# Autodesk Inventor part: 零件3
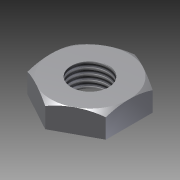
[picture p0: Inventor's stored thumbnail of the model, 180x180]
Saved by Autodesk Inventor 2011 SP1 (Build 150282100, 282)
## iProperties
Created: 2014-02
Part Number: 零件3
Document SubType Name: Modeling
Designer: yn
Density: 1 g/cm^3
Author: yn
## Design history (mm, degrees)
sketch "草图1"
  geometry: L1 (-12.633, 0)-(-12.633, -7.495); L2 (-12.633, -7.495)-(-0.037, -14.374); L3 (-0.037, -14.374)-(12.633, -7.539); L4 (12.633, -7.539)-(12.633, 0); L5 (-12.633, 0)-(-12.633, 7.495); L6 (-12.633, 7.495)-(-0.037, 14.374); L7 (-0.037, 14.374)-(12.633, 7.539); L8 (12.633, 7.539)-(12.633, 0); C1 r 6 at (0, 0); A1 r 12.633 centre (0, 0) between (12.633, 0) and (-12.633, 0); 1 further point
  constraints: 16 end point, 4 tangent, 2 centre point, 2 coincident, 2 point on circle, 1 parallel, 1 vertical
  dimensions: "d0" = 12 diameter of C1
extrude "拉伸1" new body sketch "草图1" distance "d1" = 10; taper "d2" = 0 deg
feature "螺纹1" dims "d3" = 10, "d4" = 0
sketch "草图3"
  geometry: L1 (-14.374, 10)-(-7.495, 10) reference; L2 (7.495, 10)-(14.374, 10) reference; L3 (-7.495, 10)-(7.495, 10) reference; L4 (14.374, 0)-(7.495, 0) reference; L5 (-7.495, 0)-(-14.374, 0) reference; L6 (7.495, 0)-(-7.495, 0) reference; L7 (0, 10.762)-(0, -41.632); A1 r 26.197 centre (0, -15.435) between (0, 10.762) and (0, -41.632); 1 further point
  constraints: 2 end point, 2 point on circle, 1 centre point, 1 perpendicular
revolve "旋转1" sketch "草图3" stored, may be unused: angle "d5" = 90 deg
sketch "草图5"
  geometry: L1 (-7.514, 25.802)-(12.265, 25.802); L2 (12.265, 25.802)-(12.265, -8.559); L3 (12.265, -8.559)-(-7.514, -8.559); L4 (-7.514, -8.559)-(-7.514, 25.802)
  constraints: 8 end point, 2 parallel, 1 horizontal, 1 perpendicular
extrude "拉伸2" sketch "草图5" distance "d6" = 30; taper "d7" = 0 deg
node "实体1"
